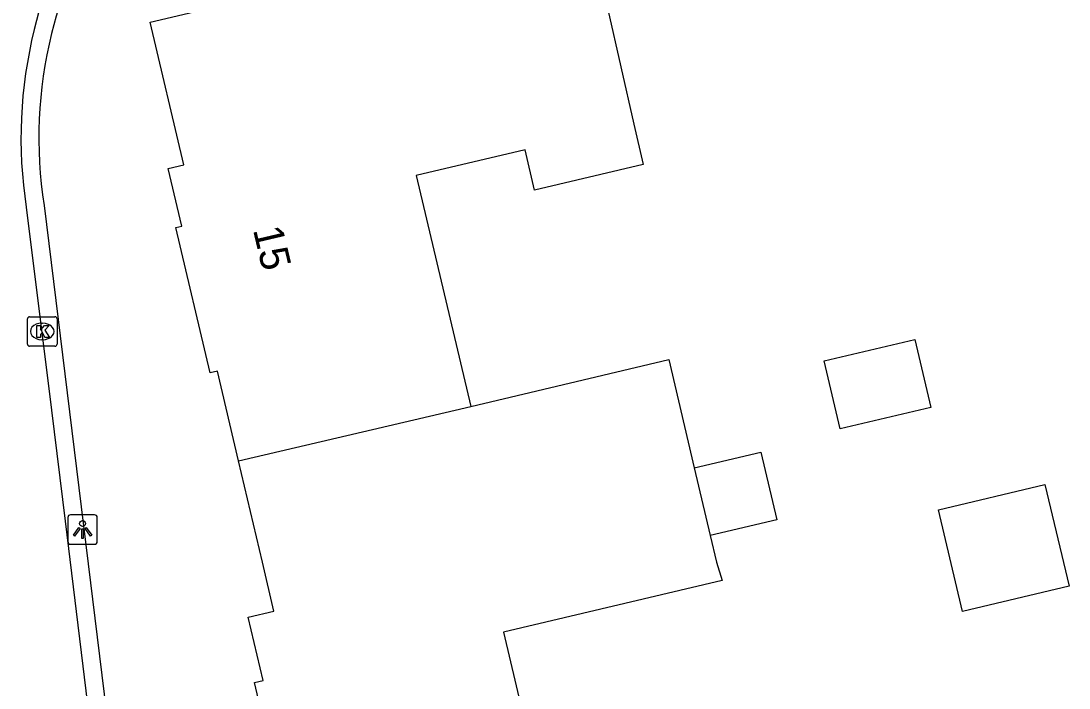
# Model space of a CAD drawing. Extents: x 157663 to 158496, y 379212 to 380934.
# Drawn here: x 158156.38 to 158191.83, y 380495.74 to 380518.31 of the extents above; entities that cross this region are included whole.
import ezdxf

# ---------------------------------------------------------------- set-up
doc = ezdxf.new("R2010")
doc.units = 0
for name, color, linetype in [('IMGEO_Kolk', 7, 'Continuous'), ('IMGEO_Lichtpunt', 7, 'Continuous'), ('IMGEO_Pand', 7, 'Continuous'), ('IMGEO_Pand_nummerreeks', 7, 'Continuous'), ('IMGEO_Rijbaan_lokaal_open', 7, 'Continuous'), ('IMGEO_Voetpad_open', 7, 'Continuous')]:
    doc.layers.add(name, color=color, linetype=linetype)

msp = doc.modelspace()

# ---------------------------------------------------------------- linework, layer by layer
at = {"layer": 'IMGEO_Kolk'}
for p, q in [((158156.672, 380508.302), (158157.524, 380508.302)), ((158156.597, 380507.376), (158156.597, 380508.228)), ((158157.085, 380508.082), (158157.11, 380508.082)), ((158157.598, 380508.228), (158157.598, 380507.376)), ((158157.524, 380507.302), (158156.672, 380507.302)), ((158157.108, 380507.522), (158157.083, 380507.522))]:
    msp.add_line(p, q, dxfattribs=at)
for points in [[(158156.672, 380508.302), (158157.524, 380508.302)], [(158156.597, 380507.376), (158156.597, 380508.228)], [(158156.918, 380508.002), (158157.041, 380508.002), (158157.041, 380507.851), (158157.171, 380508.002), (158157.335, 380508.002), (158157.189, 380507.851), (158157.342, 380507.602), (158157.19, 380507.602), (158157.105, 380507.766), (158157.041, 380507.699), (158157.041, 380507.602), (158156.918, 380507.602), (158156.918, 380508.002)], [(158157.598, 380508.228), (158157.598, 380507.376)], [(158157.524, 380507.302), (158156.672, 380507.302)]]:
    msp.add_lwpolyline(points, dxfattribs=at)
for centre, start, end in [((158156.674, 380508.226), 91.552, 178.448), ((158156.674, 380508.226), 91.552, 178.448), ((158157.522, 380508.226), 1.552, 88.448), ((158157.522, 380508.226), 1.552, 88.448), ((158156.674, 380507.378), 181.552, 268.448), ((158156.674, 380507.378), 181.552, 268.448), ((158157.522, 380507.378), 271.552, 358.448), ((158157.522, 380507.378), 271.552, 358.448)]:
    msp.add_arc(centre, 0.0765, start, end, dxfattribs=at)
for centre, major_axis, ratio, start_param, end_param in [((158157.084, 380507.802), (-0.387, 0.002), 0.722429, 4.712389, 7.853982), ((158157.109, 380507.802), (-0.39, 0.002), 0.717154, 1.570796, 4.712389)]:
    msp.add_ellipse(centre, major_axis=major_axis, ratio=ratio, start_param=start_param, end_param=end_param, dxfattribs=at)
at = {"layer": 'IMGEO_Lichtpunt'}
for p, q in [((158158.865, 380501.599), (158158.057, 380501.599)), ((158158.865, 380501.599), (158158.057, 380501.599)), ((158157.963, 380501.504), (158157.963, 380500.697)), ((158157.963, 380501.504), (158157.963, 380500.697)), ((158158.959, 380500.697), (158158.959, 380501.504)), ((158158.959, 380500.697), (158158.959, 380501.504)), ((158158.057, 380500.603), (158158.865, 380500.603)), ((158158.057, 380500.603), (158158.865, 380500.603))]:
    msp.add_line(p, q, dxfattribs=at)
for points in [[(158158.337, 380501.168), (158158.376, 380501.14), (158158.188, 380500.878), (158158.15, 380500.905), (158158.337, 380501.168)], [(158158.439, 380501.12), (158158.486, 380501.12), (158158.486, 380500.798), (158158.439, 380500.798), (158158.439, 380501.12)], [(158158.549, 380501.14), (158158.587, 380501.167), (158158.774, 380500.905), (158158.735, 380500.877), (158158.549, 380501.14)]]:
    msp.add_lwpolyline(points, dxfattribs=at)
msp.add_circle((158158.462, 380501.302), 0.0994, dxfattribs=at)
for centre, start, end in [((158158.057, 380501.504), 90, 180), ((158158.057, 380501.504), 90, 180), ((158158.865, 380501.504), 0, 90), ((158158.865, 380501.504), 0, 90), ((158158.057, 380500.697), 180, 270), ((158158.057, 380500.697), 180, 270), ((158158.865, 380500.697), 270, 0), ((158158.865, 380500.697), 270, 360)]:
    msp.add_arc(centre, 0.0946, start, end, dxfattribs=at)
at = {"layer": 'IMGEO_Pand'}
for points in [[(158163.742, 380503.42), (158163.028, 380506.456), (158162.778, 380506.397), (158161.618, 380511.317), (158161.82, 380511.364), (158161.36, 380513.312), (158161.89, 380513.437), (158160.75, 380518.271), (158170.055, 380520.465), (158175.513, 380521.752)], [(158176.232, 380518.691), (158177.114, 380514.813), (158177.423, 380513.454), (158173.752, 380512.588), (158173.432, 380513.944), (158169.75, 380513.076), (158171.592, 380505.268)], [(158184.095, 380504.507), (158183.553, 380506.809), (158186.62, 380507.532), (158187.163, 380505.231), (158184.095, 380504.507)], [(158171.592, 380505.268), (158178.293, 380506.848), (158179.155, 380503.191)], [(158163.742, 380503.42), (158171.592, 380505.268)], [(158179.155, 380503.191), (158181.403, 380503.721), (158181.944, 380501.429), (158179.696, 380500.899)], [(158166.611, 380487.799), (158165.8, 380491.229), (158165.409, 380491.136), (158164.278, 380495.921), (158164.571, 380495.991), (158164.065, 380498.13), (158164.937, 380498.336), (158164.546, 380500), (158163.742, 380503.42)], [(158179.155, 380503.191), (158179.696, 380500.899)], [(158191.835, 380499.18), (158188.23, 380498.327), (158187.416, 380501.771), (158191.021, 380502.624), (158191.835, 380499.18)], [(158179.696, 380500.899), (158179.908, 380500), (158180.1, 380499.38), (158172.701, 380497.63), (158174.566, 380489.746)]]:
    msp.add_lwpolyline(points, dxfattribs=at)
at = {"layer": 'IMGEO_Rijbaan_lokaal_open'}
msp.add_lwpolyline([(158162.104, 380467.3), (158161.202, 380474.058), (158159.819, 380485.438), (158159.338, 380489.435), (158157.889, 380501.383), (158157.419, 380505.143), (158156.56, 380512.003)], dxfattribs=at)
for centre, radius, start, end in [((158175.094, 380513.561), 18.801, 150.921, 166.3009), ((158171.544, 380514.346), 15.167, 166.0074, 188.8861)]:
    msp.add_arc(centre, radius, start, end, dxfattribs=at)
at = {"layer": 'IMGEO_Voetpad_open'}
msp.add_lwpolyline([(158157.161, 380512.065), (158162.55, 380468.158), (158162.704, 380467.421)], dxfattribs=at)
for centre, radius, start, end in [((158175.74, 380513.344), 18.88, 151.3739, 166.0883), ((158171.808, 380514.343), 14.823, 166.1817, 188.8384)]:
    msp.add_arc(centre, radius, start, end, dxfattribs=at)

# ---------------------------------------------------------------- texts
at = {"layer": 'IMGEO_Pand_nummerreeks'}
msp.add_text('15', height=1, rotation=283.2638, dxfattribs=at).set_placement((158164.224, 380511.247))

doc.saveas('drawing.dxf')
